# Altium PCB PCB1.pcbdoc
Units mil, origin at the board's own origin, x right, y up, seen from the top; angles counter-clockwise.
Board outline 3897.64 x 2283.46 mil, 4 copper layers (Top Layer, Inner1, Inner2, Bottom Layer), stack 62.447 mil thick; 82 components, 48 nets, 260 pads, 206 vias.
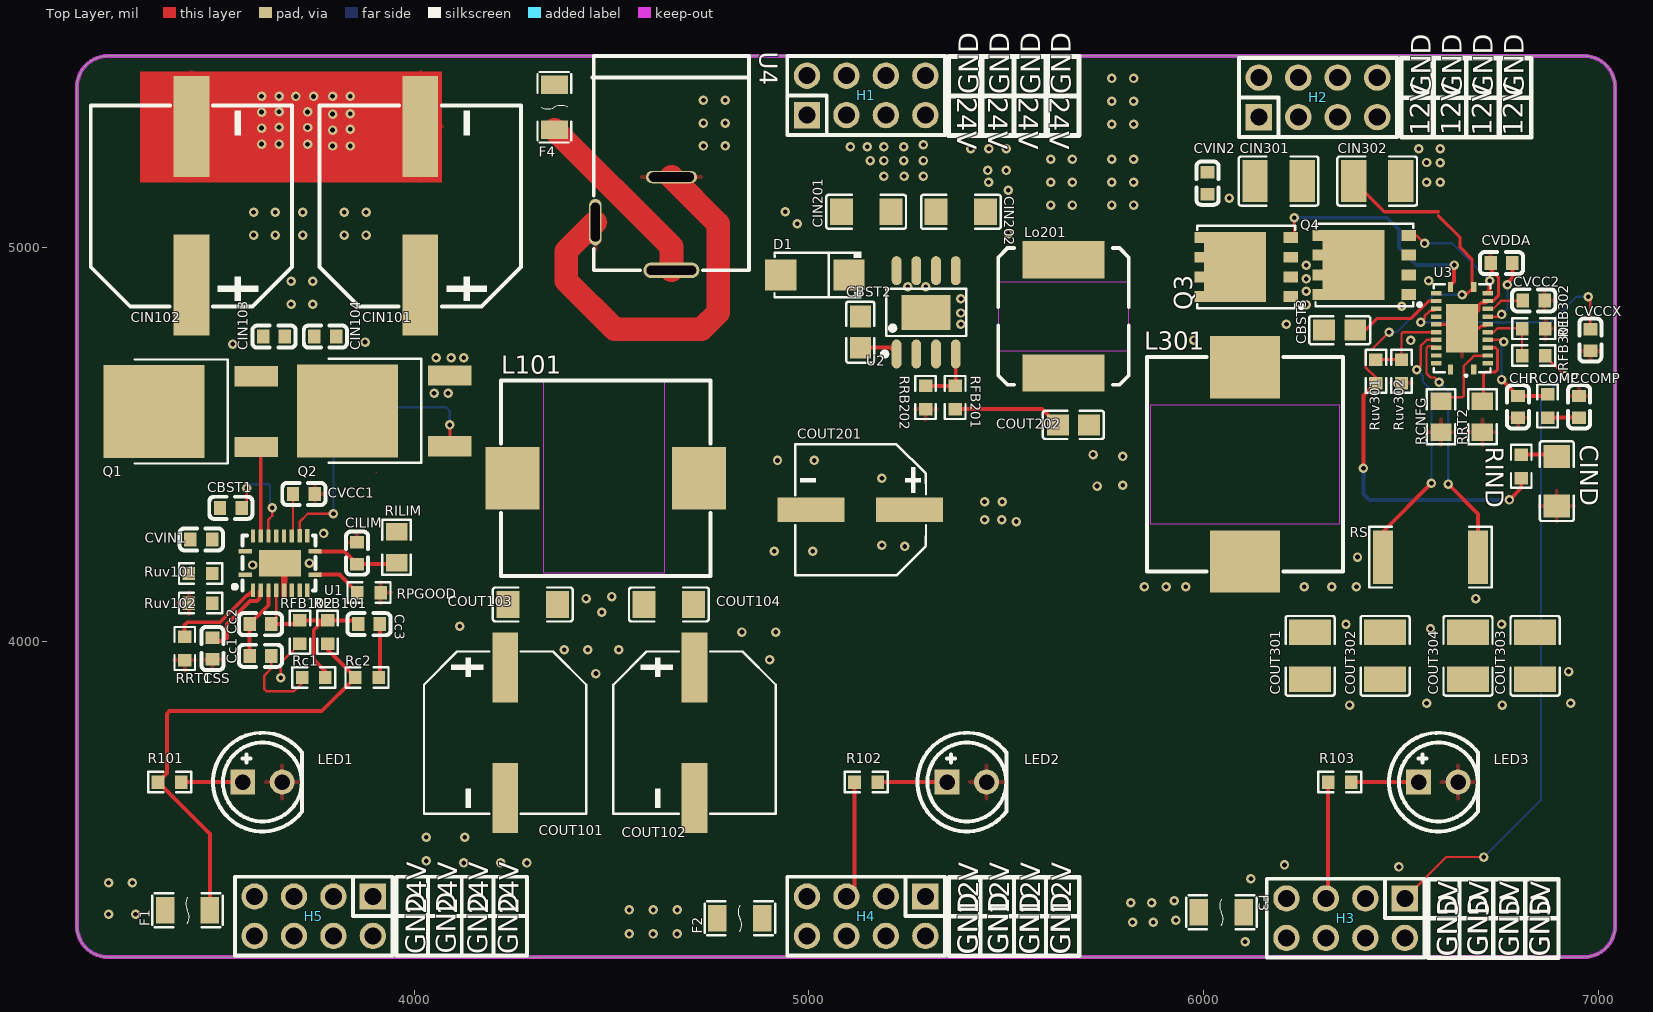
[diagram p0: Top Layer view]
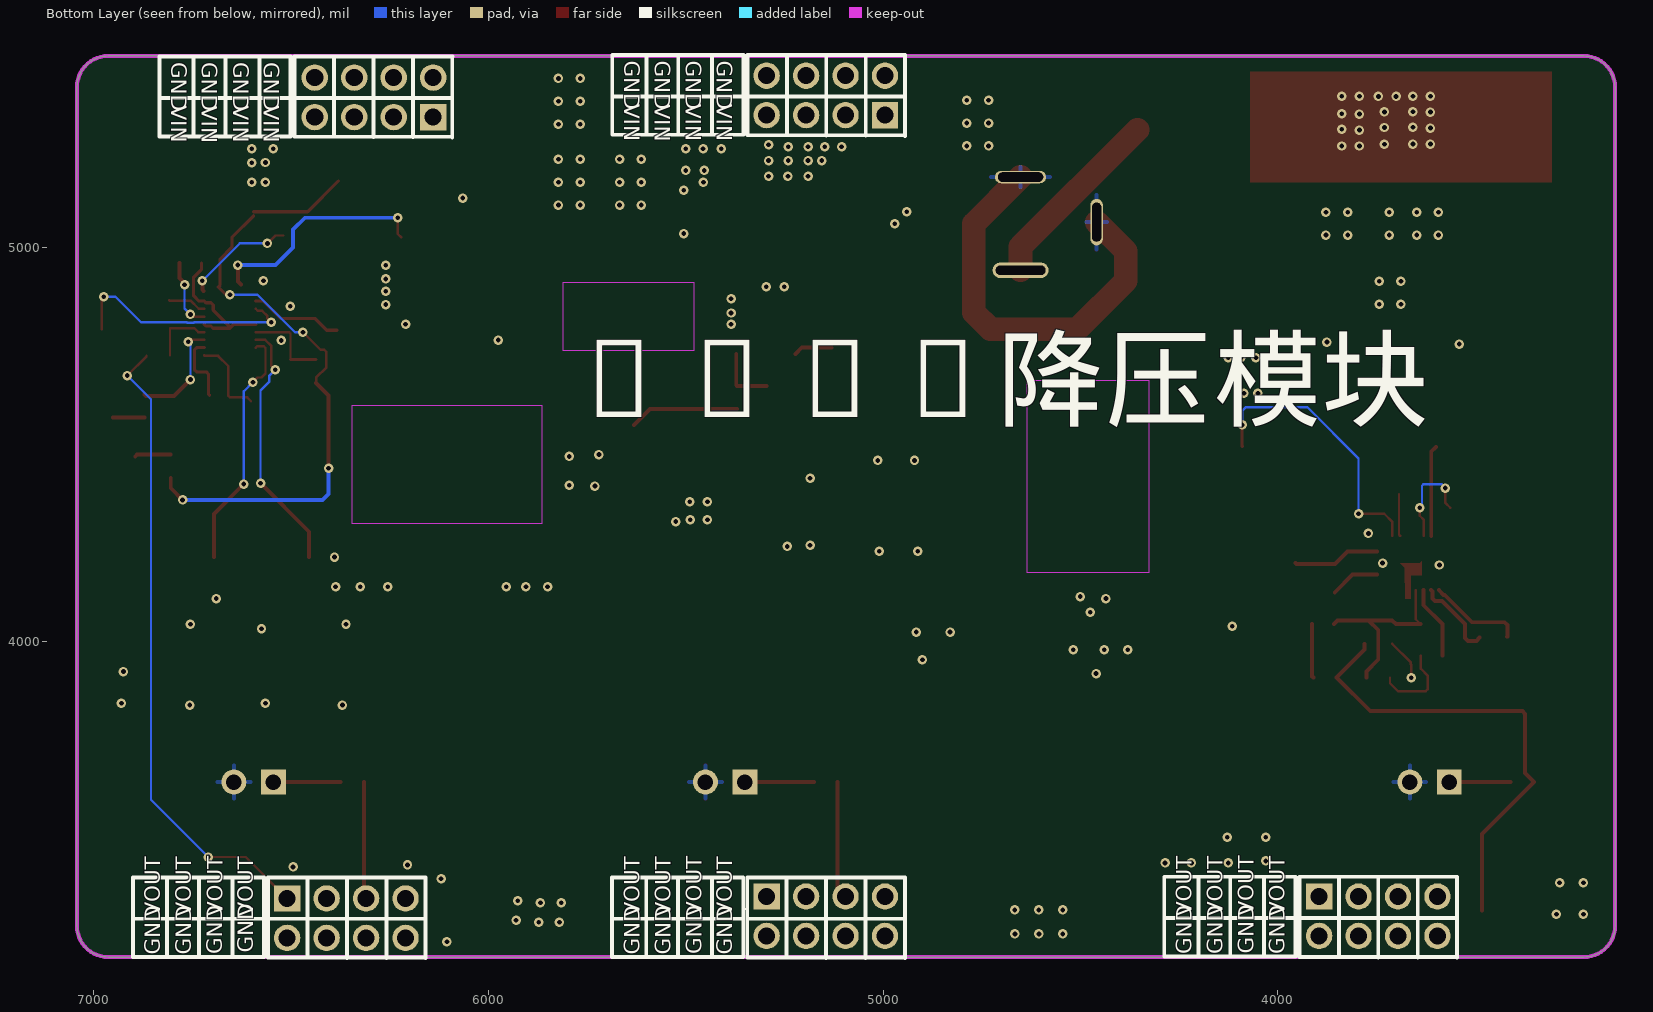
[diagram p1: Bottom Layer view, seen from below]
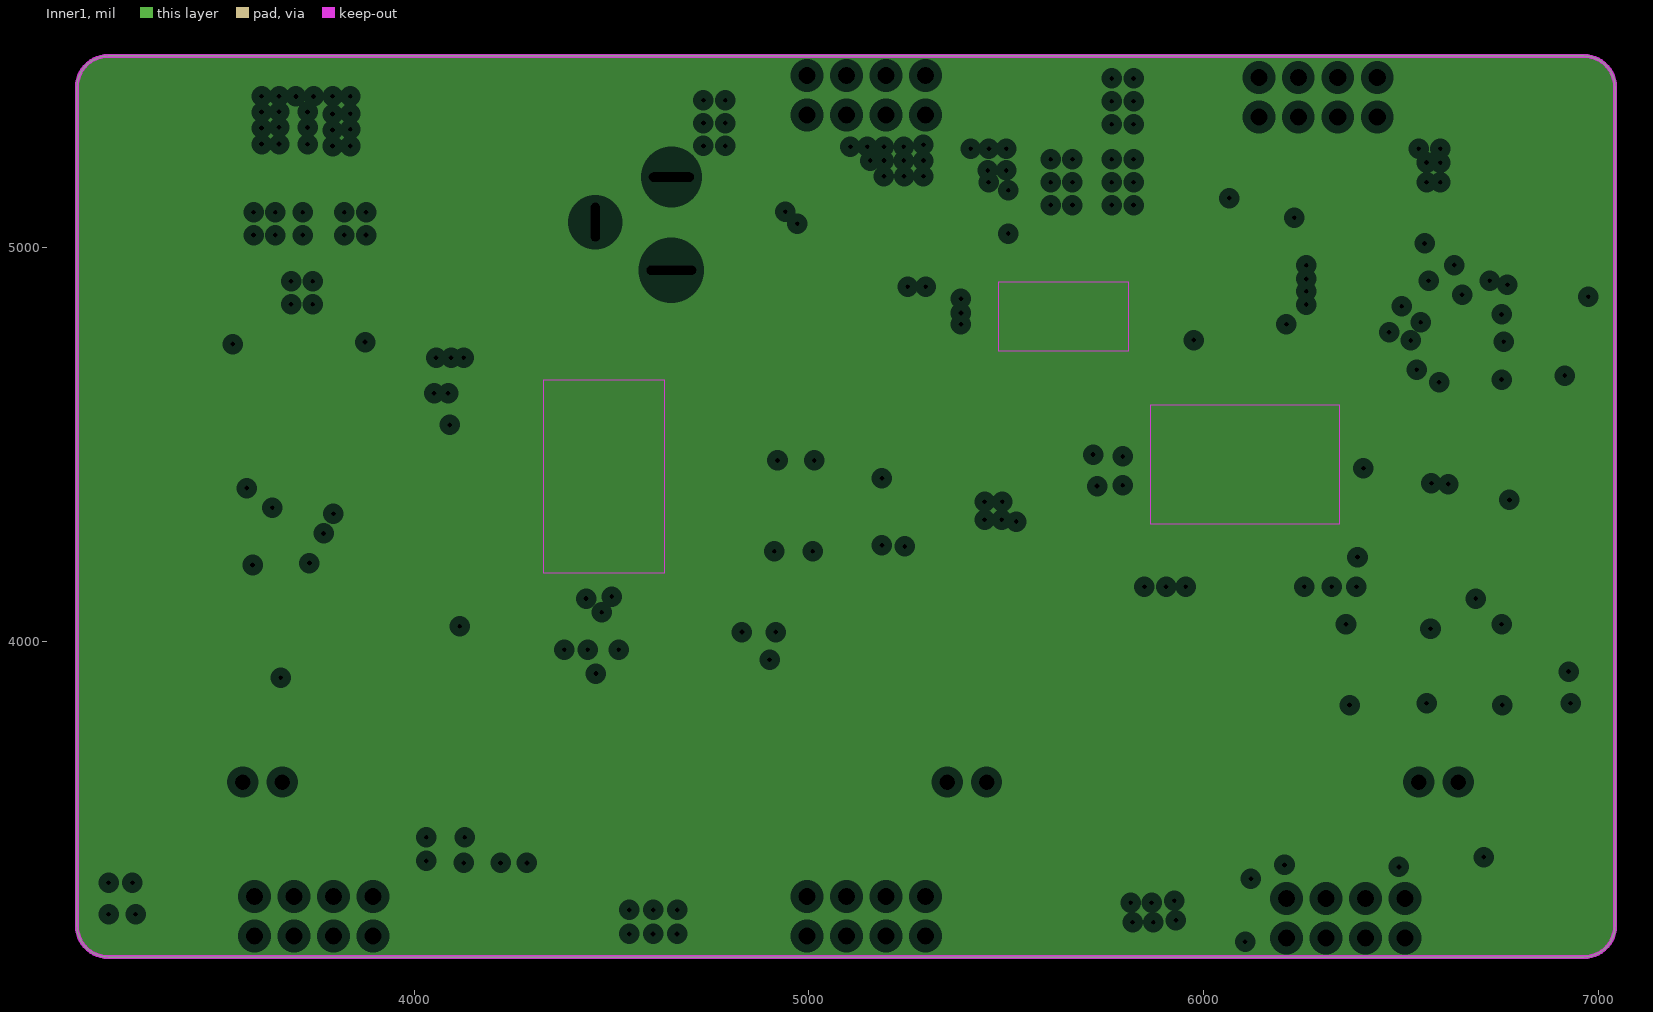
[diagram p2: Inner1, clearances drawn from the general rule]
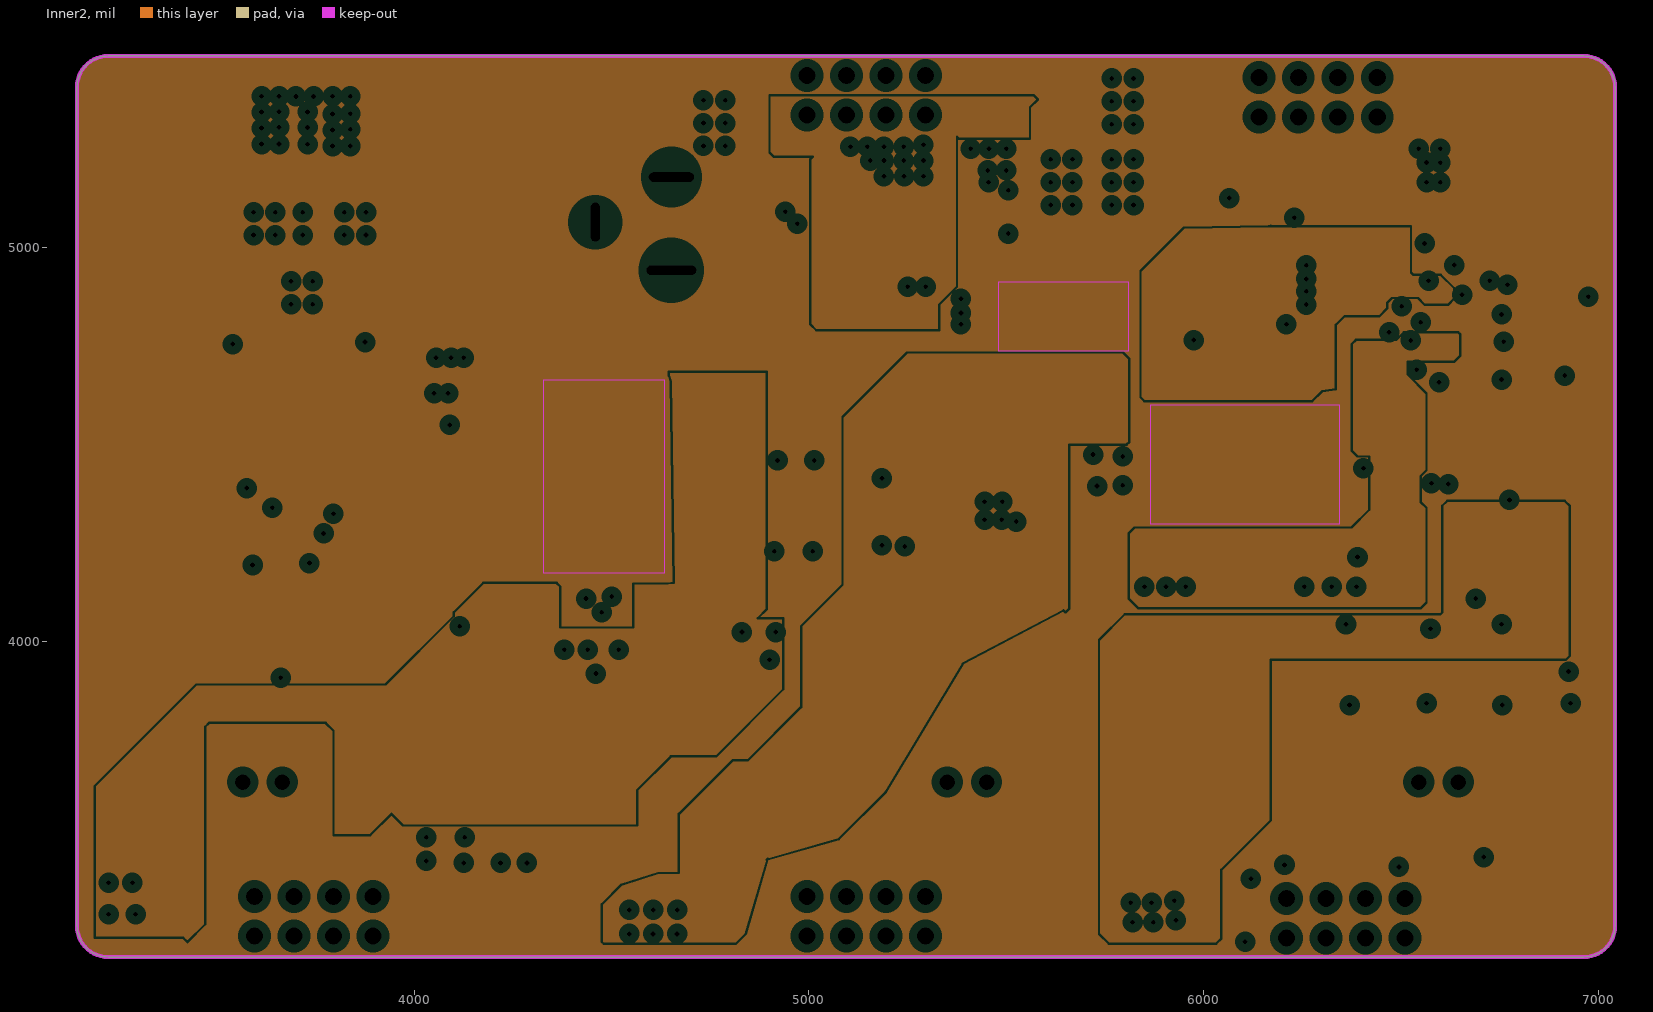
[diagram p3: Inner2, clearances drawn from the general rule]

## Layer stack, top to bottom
Top Layer: signal copper 1.378
Dielectric1: surface 8.283, 7628 RC49% 8.6mil, Dk 0
Inner1: plane copper 0.598
Dielectric2: surface 41.929, 1.1mm H/HOZ Copper, Dk 0
Inner2: plane copper 0.598
Dielectric3: surface 8.283, 7628 RC49% 8.6mil, Dk 0
Bottom Layer: signal copper 1.378

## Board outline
3223.74,5485 ccw(c3223.74,5406.26) 3145,5406.26 3145,3280.28 ccw(c3223.74,3280.28) 3223.74,3201.54 6963.9,3201.54 ccw(c6963.9,3280.28) 7042.64,3280.28 7042.64,5406.26 ccw(c6963.9,5406.26) 6963.9,5485 3223.74,5485

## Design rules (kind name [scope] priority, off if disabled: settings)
BoardOutlineClearance copperThickness1oz [All] p0: genericclearance=10 ignorepadtopadclearanceinfootprint=FALSE except(0: Arc-SplitContinuation Track-SplitContinuation SMDPad-SplitContinuation THPad-SplitContinuation Via-SplitContinuation Fill-SplitContinuation Poly-SplitContinuation Region-SplitContinuation Text-SplitContinuation)
BoardOutlineClearance copperThickness2oz [All] p0: genericclearance=10 ignorepadtopadclearanceinfootprint=FALSE except(0: Arc-SplitContinuation Track-SplitContinuation SMDPad-SplitContinuation THPad-SplitContinuation Via-SplitContinuation Fill-SplitContinuation Poly-SplitContinuation Region-SplitContinuation Text-SplitContinuation)
BoardOutlineClearance otherClearance [All] p0: genericclearance=10 ignorepadtopadclearanceinfootprint=FALSE except(0: Arc-SplitContinuation Track-SplitContinuation SMDPad-SplitContinuation THPad-SplitContinuation Via-SplitContinuation Fill-SplitContinuation Poly-SplitContinuation Region-SplitContinuation Text-SplitContinuation)
Clearance copperThickness1oz [All] p1: gap=7 ignorepadtopadclearanceinfootprint=FALSE
Clearance copperThickness2oz [All] p1: gap=7 ignorepadtopadclearanceinfootprint=FALSE
Clearance otherClearance [All] p1: gap=7 ignorepadtopadclearanceinfootprint=FALSE
DiffPairsRouting differentialPair [All] p1: maxuncoupledlength=10 minlimit=6 maxlimit=Infinity mostfreqgap=6 toplayer_minwidth=5 toplayer_prefwidth=10 toplayer_maxwidth=100 bottomlayer_minwidth=5 bottomlayer_prefwidth=10 bottomlayer_maxwidth=100
PasteMaskExpansion pasteMaskExpansion [All] p1: expansion=0
PlaneConnect innerPlane [All] p1: planeconnectstyle=Relief reliefexpansion=20 reliefentries=4 reliefconductorwidth=10 reliefairgap=10
PolygonConnect copperRegion [All] p1: connectstyle=Relief reliefentries=4 reliefconductorwidth=10 polygonreliefangle="90 Angle" airgapwidth=10
RoutingVias viaSize [All] p1: viastyle="Through Hole" holewidth=12.0078 minholewidth=11.811 maxholewidth=248.0314 width=12.0078 minwidth=11.811 maxwidth=248.0314
SolderMaskExpansion solderMaskExpansion [IsVia] p1: useseparateexpansions=TRUE expansion=-1000 expansionbottom=-1000
SolderMaskExpansion solderMaskExpansion [All] p2: useseparateexpansions=TRUE expansion=2 expansionbottom=2
Width copperThickness1oz [All] p1: maxlimit=100 minlimit=5 preferedwidth=10
Width copperThickness2oz [All] p1: maxlimit=100 minlimit=8 preferedwidth=10

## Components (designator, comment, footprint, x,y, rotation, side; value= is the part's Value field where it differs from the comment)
CBST1 "100nF" C0603 3535,4340 r180 top
CBST2 "10nF" C0805 5130,4785 r90 top
CBST3 "100nF" C0805 6345,4790 r0 top
Cc1 "4.7nF" C0603 3610,3965 r180 top
Cc2 "82pF" C0603 3610,4045 r180 top
Cc3 "1.8nF" C0603 3885,4045 r0 top
CCOMP "8.2nF" C0603 6951.61,4595.77 r270 top
CHF "180pF" C0603 6796.61,4595.77 r90 top
CILIM "4.7nF" C0603 3855,4225 r90 top
CIN101 "100uF" CAP-SMD_BD12.5-L13.0-W13.0-LS13.7-FD 4015,5105 r90 top
CIN102 "100uF" CAP-SMD_BD12.5-L13.0-W13.0-LS13.7-FD 3435,5105 r90 top
CIN103 "100nF" C0603 3644.38,4773.86 r0 top
CIN104 "100nF" C0603 3774.38,4773.86 r180 top
CIN201 "22uf" C1206 5145,5090 r0 top
CIN202 "10uF" C1206 5385,5090 r180 top
CIN301 "22uF" C1210 6190,5168 r0 top
CIN302 "22uF" C1210 6440,5168 r180 top
CIND "47uF" C1206 6895,4407.3 r90 top
COUT101 "220uF" CAP-SMD_BD10.0-L10.3-W10.3-LS11.7-FD 4230,3770 r270 top
COUT102 "220uF" CAP-SMD_BD10.0-L10.3-W10.3-LS11.7-FD 4710,3770 r270 top
COUT103 "10uF" C1206 4300,4095 r180 top
COUT104 "10uF" C1206 4645,4095 r0 top
COUT201 "220uF" CAP-SMD_BD8.0-L8.3-W8.3-LS9.3-FD-A 5130,4335 r180 top
COUT202 "10uF" C0805 5670,4550 r180 top
COUT301 "47uF" C1210 6270,3965 r90 top
COUT302 "47uF" C1210 6460,3965 r90 top
COUT303 "47uF" C1210 6840,3965 r90 top
COUT304 "47uF" C1210 6670,3965 r90 top
CSS "47nF" C0603 3488.27,3983.49 r90 top
CVCC1 "2.2uF" C0603 3720,4375 r0 top
CVCC2 "2.2uF" C0603 6836.61,4865.77 r0 top
CVCCX "100nF" C0603 6980,4765 r90 top
CVDDA "100nF" C0603 6755,4960 r0 top
CVIN1 "100nF" C0603 3460,4260 r180 top
CVIN2 "22nF" C0603 6010,5162.57 r270 top
D1 "SS36" SMA_L4.3-W2.6-LS5.2-RD 5015,4930 r180 top
F1 "JFC1206-1300FS" F1206 3425,3320 r0 top
F2 "JFC1206-1300FS" F1206 4825,3300 r0 top
F3 "JFC1206-1300FS" F1206 6045,3315 r0 top
F4 "JFC1206-1300FS" F1206 4355,5355 r90 top
H1 "" HDR-TH_8P-P2.54-V-M-R2-C4-S2.54 5145,5385 r0 top
H2 "" HDR-TH_8P-P2.54-V-M-R2-C4-S2.54 6290,5380 r0 top
H3 "" HDR-TH_8P-P2.54-V-M-R2-C4-S2.54 6360,3300 r180 top
H4 "" HDR-TH_8P-P2.54-V-M-R2-C4-S2.54 5145,3305 r180 top
H5 "" HDR-TH_8P-P2.54-V-M-R2-C4-S2.54 3745,3305 r180 top
L101 "XR1250-4R7M" IND-SMD_L13.5-W12.6 4485,4415 r0 top
L301 "SMMS1360-2R2M" IND-SMD_L13.8-W12.6_SMMS1360 6105,4450 r270 top
LED1 "" LED-TH_5mm 3615,3645 r0 top
LED2 "" LED-TH_5mm 5400,3645 r0 top
LED3 "" LED-TH_5mm 6595,3645 r0 top
Lo201 "33uH" IND-SMD_L8.2-W8.2-LS8.6 5645,4825 r270 top
Q1 "NCE0110K" TO-252-2_L6.6-W6.1-P4.57-LS9.9-TL-CW 3469.38,4583.86 r180 top
Q2 "NCE0110K" TO-252-2_L6.6-W6.1-P4.57-LS9.9-TL-CW 3960.05,4585.37 r180 top
Q3 "BSC027N04LSG" PG-TDSON-8_L5.0-W6.0-P1.27-LS6.2-BL-EP 6107.77,4949.99 r90 top
Q4 "BSC027N04LSG" PG-TDSON-8_L5.0-W6.0-P1.27-LS6.2-BL-EP 6407.48,4955.13 r90 top
R101 "2K" R0603 3380,3645 r0 top
R102 "1K" R0603 5145,3645 r0 top
R103 "330Ω" R0603 6345,3645 r0 top
Rc1 "10.2K" R0603 3745,3910 r0 top
Rc2 "107Ω" R0603 3880,3910 r180 top
RCNFG "41.2kΩ" R0805 6601.61,4570.77 r90 top
RCOMP "5.23kΩ" R0603 6871.61,4597.96 r90 top
RFB101 "22.1K" R0603 3780,4025 r270 top
RFB102 "768Ω" R0603 3710,4025 r270 top
RFB201 "10kΩ" R0603 5370.5,4619.5 r270 top
RFB301 "78.7kΩ" R0603 6836.61,4725.77 r180 top
RFB302 "15kΩ" R0603 6836.61,4793.87 r180 top
RILIM "19.6K" R0805 3955,4240 r90 top
RIND "250mΩ" R0603 6805,4445 r270 top
RPGOOD "20K" R0603 3885,4125 r180 top
RRB202 "1.13kΩ" R0603 5295.5,4619.5 r90 top
RRT1 "24.9K" R0603 3418.27,3983.49 r90 top
RRT2 "73.2kΩ" R0805 6706.61,4570.77 r90 top
RS "2mΩ" R2512 6575,4215 r0 top
Ruv101 "402K" R0603 3458.27,4173.49 r180 top
Ruv102 "14.7K" R0603 3458.27,4098.49 r0 top
Ruv301 "100kΩ" R0603 6436.61,4685.77 r90 top
Ruv302 "10.5kΩ" R0603 6501.61,4685.77 r270 top
U1 "LM5145RGYR" VQFN-20_L4.5-W3.5-P0.50-BL-EP 3660,4200 r0 top
U2 "TPS5430DDA" ESOP-8_L4.9-W3.9-P1.27-LS6.0-BL-EP-2 5296.93,4835.27 r0 top
U3 "LM5148RGYR" VQFN-24_L5.5-W3.5-P0.50-BL-EP-2 6655,4795 r90 top
U4 "DC-S006A-D020-5A" CONN-TH_DC-S006A-D020-5A 4555,5060 r270 top

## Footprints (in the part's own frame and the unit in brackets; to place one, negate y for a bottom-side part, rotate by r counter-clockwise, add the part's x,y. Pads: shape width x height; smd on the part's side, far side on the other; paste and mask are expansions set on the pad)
C0603 [mm]
  rect 0.8x0.9 smd: 1(-0.7,0) 2(0.7,0)
  silkscreen extent -1.39,-0.71 1.39,0.71
C0805 [mm]
  rect 1.41x1.35 smd paste-100 mask+0.051: 1(-1,0) 2(1,0)
  silkscreen extent -1.96,-0.9 1.96,0.9
C1206 [mm]
  rect 1.485x1.728 smd paste-100 mask+0.051: 1(-1.593,0) 2(1.593,0)
  silkscreen extent -2.56,-1.09 2.56,1.09
C1210 [mm]
  rect 1.635x2.7 smd paste-100 mask+0.051: 1(-1.517,0) 2(1.517,0)
  silkscreen extent -2.56,-1.58 2.56,1.58
CAP-SMD_BD8.0-L8.3-W8.3-LS9.3-FD-A [mm]
  rect 4.3x1.6 smd: 1(-3.173,0) 2(3.173,0)
  silkscreen extent -4.23,-4.23 4.18,4.23
CAP-SMD_BD10.0-L10.3-W10.3-LS11.7-FD [mm]
  rect 4.5x1.65 smd: 1(-4.2,0) 2(4.2,0)
  silkscreen extent -5.23,-5.23 5.23,5.23
CAP-SMD_BD12.5-L13.0-W13.0-LS13.7-FD [mm]
  rect 6.5x2.3 smd: 1(-5.1,0) 2(5.1,0)
  silkscreen extent -6.48,-6.48 6.48,6.48
CONN-TH_DC-S006A-D020-5A [mm]
  oval 1x3.6 hole 0.6 slot 3.2 at 90 deg paste+0 mask+0.05: 1(3,2.45)
  oval 0.8x3.3 hole 0.6 slot 2.9 at 90 deg paste+0 mask+0.05: 2(-3,2.45)
  oval 3x0.8 hole 0.6 slot 2.5 at 0 deg paste+0 mask+0.05: 3(-0.1,-2.45)
  silkscreen extent -10.8,-2.63 3,7.45
ESOP-8_L4.9-W3.9-P1.27-LS6.0-BL-EP-2 [mm]
  oval 0.63x1.865 smd: 1(-1.905,-2.683) 2(-0.635,-2.683) 3(0.635,-2.683) 4(1.905,-2.683) 5(1.905,2.682) 6(0.635,2.682) 7(-0.635,2.682) 8(-1.905,2.682)
  rect 3.15x2.26 smd paste+0 mask+0.05: 9(0,0)
  silkscreen extent -2.82,-2.83 2.58,1.52
F1206 [mm]
  rect 1.19x1.728 smd: 1(-1.445,0) 2(1.445,0)
  silkscreen extent -2.27,-1.09 2.27,1.09
HDR-TH_8P-P2.54-V-M-R2-C4-S2.54 [mm]
  rect 1.7x1.7 hole 1.1: 1(-3.81,-1.27)
  round 1.7 hole 1.1: 2(-3.81,1.27) 3(-1.27,-1.27) 4(-1.27,1.27) 5(1.27,-1.27) 6(1.27,1.27) 7(3.81,-1.27) 8(3.81,1.27)
  silkscreen extent -5.08,-2.54 5.08,2.54
IND-SMD_L8.2-W8.2-LS8.6 [mm]
  rect 2.4x5.3 smd: 1(-3.638,0) 2(3.638,0)
  silkscreen extent -4.4,-4.2 4.4,4.2
IND-SMD_L13.5-W12.6 [mm]
  rect 3.5x4 smd: 1(-6,0) 2(6,0)
  silkscreen extent -6.75,-6.3 6.75,6.3
IND-SMD_L13.8-W12.6_SMMS1360 [mm]
  rect 4x4.5 smd: 1(-6.25,0) 2(6.25,0)
  silkscreen extent -6.9,-6.3 6.9,6.3
LED-TH_5mm [mm]
  rect 1.6x1.6 hole 1 paste+0 mask+0.051: 1(-1.27,0)
  round 1.6 hole 1 paste+0 mask+0.051: 2(1.27,0)
  silkscreen extent -3.17,-3.17 2.54,3.17
PG-TDSON-8_L5.0-W6.0-P1.27-LS6.2-BL-EP [mm]
  rect 0.7x0.925 smd paste-100 mask+0.051: 1(-1.905,-2.865) 2(-0.635,-2.865) 3(0.635,-2.865) 4(1.905,-2.865) 5(1.905,2.865) 6(0.635,2.865) 7(-0.635,2.865) 8(-1.905,2.865)
  rect 4.5x4 smd paste-100 mask+0.05: 9(0,0.705)
  silkscreen extent -2.66,-3.66 2.65,3.15
R0603 [mil]
  rect 31.75x34.02 smd paste-3937.01 mask+2: 1(-29.66,0) 2(29.66,0)
  silkscreen extent -55,-26 55,26
R0805 [mil]
  rect 44.59x54.21 smd paste-3937.01 mask+2: 1(-39.37,0) 2(39.37,0)
  silkscreen extent -69,-36 69,36
R2512 [mil]
  rect 50.49x136.06 smd paste-3937.01 mask+2: 1(-120.72,0) 2(120.72,0)
  silkscreen extent -155,-77 155,77
SMA_L4.3-W2.6-LS5.2-RD [mm]
  rect 2x2 smd: 1(-2.2,0) 2(2.2,0)
  silkscreen extent -2.98,-1.5 2.6,1.5
TO-252-2_L6.6-W6.1-P4.57-LS9.9-TL-CW [mm]
  rect 2.8x1.3 smd: 1(-3.292,2.273) 3(-3.292,-2.273)
  rect 6.5x6 smd: 2(3.292,0)
  silkscreen extent -1.46,-3.35 4.51,3.34
VQFN-20_L4.5-W3.5-P0.50-BL-EP [mm]
  rect 0.85x0.28 smd: 1(-2.25,-0.752) 10(2.25,-0.752) 11(2.25,0.748) 20(-2.25,0.75)
  rect 0.28x0.85 smd: 2(-1.749,-1.75) 3(-1.248,-1.75) 4(-0.749,-1.75) 5(-0.248,-1.75) 6(0.251,-1.75) 7(0.752,-1.75) 8(1.251,-1.75) 9(1.752,-1.75) 12(1.752,1.75) 13(1.251,1.75) 14(0.75,1.748) 15(0.25,1.748) 16(-0.25,1.748) 17(-0.75,1.748) 18(-1.25,1.748) 19(-1.75,1.748)
  rect 2.7x1.7 smd: 21(0,-0.002)
  silkscreen extent -3.05,-1.78 2.29,1.78
VQFN-24_L5.5-W3.5-P0.50-BL-EP-2 [mm]
  rect 0.665x0.336 smd: 1(-2.657,-0.75) 12(2.657,-0.75) 13(2.657,0.75) 24(-2.657,0.75)
  rect 0.28x0.665 smd: 2(-2.25,-1.657) 3(-1.75,-1.657) 4(-1.25,-1.657) 5(-0.75,-1.657) 6(-0.25,-1.657) 7(0.25,-1.657) 8(0.75,-1.657) 9(1.25,-1.657) 10(1.75,-1.657) 11(2.25,-1.657) 14(2.25,1.657) 15(1.75,1.657) 16(1.25,1.657) 17(0.75,1.657) 18(0.25,1.657) 19(-0.25,1.657) 20(-0.75,1.657) 21(-1.25,1.657) 22(-1.75,1.657) 23(-2.25,1.657)
  rect 3.1x2.05 smd: 25(0,0)
  silkscreen extent -3.12,-1.83 2.83,1.83

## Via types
v1: diameter 24.02, hole 12, Top Layer to Bottom Layer, 206 vias

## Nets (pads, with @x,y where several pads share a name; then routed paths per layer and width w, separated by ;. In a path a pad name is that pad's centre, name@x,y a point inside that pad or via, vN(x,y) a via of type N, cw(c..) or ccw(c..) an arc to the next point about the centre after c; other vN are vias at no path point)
$1N88: LED1.1 R101.2 | length 155.3
  Top Layer w10: R101.2 LED1.1
$1N109: COUT201.1 COUT202.2 F2.1 Lo201.2 RFB201.2 | length 276.6
  Top Layer w10: RFB201.2 5590.79,4589.84 COUT202.2
  other v1: 4544.3,3260 4605,3260 4665.7,3260 4544.65,3320.85 4605.35,3320.85 4666.04,3320.85 5242.77,4242.17 5185,4245 5185,4415
$1N113: LED2.1 R102.2 | length 175.3
  Top Layer w10: R102.2 LED2.1
$1N116: LED3.1 R103.2 | length 170.3
  Top Layer w10: R103.2 LED3.1
$1N123: Cc1.1 Rc1.1 | length 212.8
  Top Layer w6: Cc1.1 3637.56,3932.56 3620,3915 3620,3880 3625,3875 3695,3875 3715.34,3895.34 Rc1.1
$1N125: Cc3.2 Rc2.1 | length 136.2
  Top Layer w10: Rc2.1 3912.56,3912.9 Cc3.2
$1N132: COUT101.1 COUT102.1 COUT103.2 COUT104.2 F1.1 L101.2
  other v1: 3225,3310 3293.59,3310 3225,3390 3285.7,3390 4460,3920 4900,3955 4380,3980 4439.51,3980 4517.86,3980 4830,4025 4915.87,4025 4115,4040
$1N150: F4.1 U4.1 | length 479
  Top Layer w60: F4.1 4651.45,5001.65 U4.1
$2N64: CCOMP.2 RCOMP.1 | length 80
  Top Layer w10: RCOMP.1 6951.52,4568.3 CCOMP.2
$2N105: CIND.2 RIND.1 | length 91.9
  Top Layer w10: RIND.1 6890.34,4474.66 CIND.2
BOOT_24V: CBST2.1 U2.1 | length 98.5
  Top Layer w10: CBST2.1 5205.96,4745.63 U2.1
BST_48V: CBST1.1 U1.17 | length 254
  Top Layer w6: CBST1.1 3575,4352.44 v1(3575,4390) ; U1.17 3630,4269.29 3630,4310 3640,4320 v1(3640,4340)
  Bottom Layer w6: v1(3575,4390) 3585,4400 3630,4400 3634.24,4395.76 3634.24,4345.76 v1(3640,4340)
CBOOT: CBST3.2 U3.15 | length 236
  Top Layer w8: CBST3.2 6410,4790 6440,4820 6526.4,4820 6570.3,4863.9 U3.15
CNFG: RCNFG.2 U3.3 | length 210.6
  Top Layer w6: RCNFG.2 6611.47,4620 6655,4620 6659.24,4624.24 6659.24,4699.24 6685,4725 6719.16,4725 U3.3
COMP_48V: Cc1.2 Cc2.2 U1.4 | length 186
  Top Layer w10: Cc1.2 Cc2.2 3630.53,4093.09 U1.4
EN: Ruv301.2 Ruv302.1 U3.19 | length 220.8
  Top Layer w6: Ruv302.1 6501.61,4781.61 6505,4785 6589.59,4785 U3.19
  Top Layer w8: Ruv301.2 Ruv302.1
EN/UVLO_48V: Ruv101.1 Ruv102.2 U1.1
ENA: U2.5
EXTCOMP_12V: CHF.2 RCOMP.2 U3.5 | length 275.9
  Top Layer w6: U3.5 6755.73,4765.47 v1(6760.6,4760.6)
  Top Layer w10: v1(6755,4665) CHF.2@6796.61,4623.39 ; CHF.2 6867.31,4623.33 RCOMP.2
  Bottom Layer w6: v1(6755,4665) 6755,4755 v1(6760.6,4760.6)
FB_12V: RFB301.2 RFB302.2 U3.6 | length 159.3
  Top Layer w6: U3.6 6735.15,4785.15 6745,4795 6805.81,4795 RFB302.2 RFB301.2
FB_48V: Cc2.1 Cc3.1 Rc1.2 RFB101.1 RFB102.1 U1.5 | length 486.4
  Top Layer w6: Cc2.1 3650.22,4057.66 U1.5
  Top Layer w10: Cc2.1 3700.34,4045 RFB102.1 RFB101.1@3769.66,4054.66 ; Rc1.2 3774.66,3925.34 3745,3955 3745,4030 RFB101.1@3769.66,4054.66 ; Cc3.1 3847.78,4054.66 RFB101.1 RFB101.1@3769.66,4054.66
GND: CCOMP.1 CHF.1 CILIM.2 CIN101.2 CIN102.2 CIN103.1 CIN104.1 CIN201.1 CIN202.1 CIN301.1 CIN302.1 CIND.1 COUT101.2 COUT102.2 COUT103.1 COUT104.1 COUT201.2 COUT202.1 COUT301.1 COUT302.1 COUT303.1 COUT304.1 CSS.1 CVCC1.2 CVCC2.2 CVCCX.1 CVDDA.1 CVIN2.2 D1.2 H1.2 H1.4 H1.6 H1.8 H2.2 H2.4 H2.6 H2.8 H3.2 H3.4 H3.6 H3.8 H4.2 H4.4 H4.6 H4.8 H5.2 H5.4 H5.6 H5.8 LED1.2 LED2.2 LED3.2 Q2.3 Q4.1 Q4.2 Q4.3 RCNFG.1 RFB102.2 RFB302.1 RPGOOD.1 RRB202.1 RRT1.1 RRT2.1 Ruv102.1 Ruv302.2 U1.6 U1.12 U1.15 U1.21 U2.6 U2.9 U3.7 U3.10 U3.18 U3.25 U4.2 U4.3 | length 1496.4
  Top Layer w6: v1(3661.15,3909.56) 3661.15,3942.42 3662.29,3943.56 3662.29,3947.63 RFB102.2
  Top Layer w8: U3.18 6645.16,4804.84 U3.25 ; U3.7 6716.07,4800.65 6703.03,4800.65 6697.37,4794.99 U3.25 ; CVDDA.1 6727.44,4943.68 6747.01,4924.12 6747.01,4877.01 6733.9,4863.9 U3.10 6716.06,4859.7 6703.03,4859.7 6697.18,4853.85 6697.18,4840.82 6655.01,4798.65 U3.25
  Top Layer w60: U4.3 4385,4990.39 4385,4915 4507.43,4792.57 4727.57,4792.57 4770,4835 4770,5059.56 U4.2
  other v1: 4125,3440 4218.53,3440 4285.38,3440 4030,3445 4030,3505 4127.64,3505 6370,3840 6756.81,3840 6565,3845 6930,3845 6925,3925 4475,4075 4435,4110 4500,4115 3590,4195 3733.98,4200 4911.85,4230 5009.75,4230 3770,4275 5525,4305 5445,4310 5488.76,4310 5445,4355 5490,4355 5730,4395 5795,4396.86 4920.25,4460 5013.15,4460 5795,4470 5720,4475 4050,4630 4085.49,4630 4055,4720 4093,4720 4125,4720 3540,4755 3875,4760 5385,4805.32 5385,4833.59 6502.1,4850.88 5385,4870 5505,5035 4970,5060 4940,5090 5612.5,5107.1 5667.5,5107.1 5767.5,5107.1 5822.5,5107.1 6065,5125 5505,5145 5455,5165 5612.5,5165 5667.5,5165 5767.5,5165 5822.5,5165 6565,5165 6600,5165 5453.33,5195 5500,5195 6600,5214.43 6565,5215 5612.5,5222.9 5667.5,5222.9 5767.5,5222.9 5822.5,5222.9 5410,5250 5455.97,5250 5500,5250 6545,5250 6600,5250 3792.77,5256.8 3837.23,5256.8 4732.5,5257.1 4787.5,5257.1 3729.47,5261.11 3612.77,5261.8 3657.23,5261.8 3792.77,5297.27 3837.23,5299.41 3612.77,5302.27 3657.23,5304.41 3729.47,5303.71 5767.5,5312.1 5822.5,5312.1 4732.5,5315 4787.5,5315 3792.77,5337.73 3837.23,5338.8 3612.77,5342.73 3729.47,5343.11 3657.23,5343.8 5767.5,5370 5822.5,5370 4732.5,5372.9 4787.5,5372.9 3700,5382.5 3744.47,5382.5 3612.77,5383.2 3657.23,5383.2 3792.77,5383.2 3837.23,5383.2 5767.5,5427.9 5822.5,5427.9
HO_12V: Q3.4 U3.13 | length 587.9
  Top Layer w6: Q3.4 6230,5034.42 v1(6230,5075)
  Top Layer w10: U3.13@6627.08,4905.4 6635,4913.31 v1(6635,4955)
  Bottom Layer w10: v1(6230,5075) 6465,5075 6495,5045 6495,5000 6540,4955 v1(6635,4955)
HO_48V: Q1.1 U1.18 | length 230.4
  Top Layer w10: Q1.1 3610.79,4482.57 U1.18
ILIM_48V: CILIM.1 RILIM.1 U1.11 | length 221
  Top Layer w10: U1.11 3822.99,4229.45 CILIM.1 3951.81,4197.44 RILIM.1
ISNS+: L301.2 RS.1 U3.20 | length 651.9
  Top Layer w6: v1(6540,4690) 6550,4700 6550,4750 6565.47,4765.47 U3.20
  Top Layer w10: RS.1 6454.28,4279.28 v1(6577.5,4402.5)
  Bottom Layer w6: v1(6540,4690) 6555,4675 6555,4660 6577.5,4637.5 v1(6577.5,4402.5)
  other v1: 5850,4140 5905,4140 5955,4140 6255,4140 6325,4140 6387.24,4140 6390,4215 6525,4763.99
LO_12V: Q4.4 U3.11 | length 279.4
  Top Layer w6: Q4.4 6539.87,5030.13 v1(6560,5010)
  Top Layer w10: 6721.86,4889.35 6725,4892.48 v1(6725,4915)
  Bottom Layer w6: v1(6560,5010) 6630,5010 v1(6725,4915)
LO_48V: Q2.1 U1.13 | length 711.9
  Top Layer w6: U1.13 3709.27,4304.27 3730,4325 v1(3795,4325)
  Top Layer w8: Q2.1 4090,4496.24 v1(4090,4550)
  Bottom Layer w6: v1(3795,4325) 3795,4465 3925,4595 4080,4595 4090,4585 v1(4090,4550)
NC: U1.16
PGOOD_48V: RPGOOD.2 U1.10 | length 125.6
  Top Layer w10: U1.10 3809.95,4170.39 RPGOOD.2
PH: CBST2.2 D1.1 Lo201.1 U2.8
RT_12V: RRT2.2 U3.4 | length 172.2
  Top Layer w8: RRT2.2@6706.61,4625.14 6709.34,4627.88 6709.34,4678.69 6715,4684.34 6739.34,4684.34 6745,4690 6745,4740 6739.22,4745.78 U3.4
RT_48V: RRT1.2 U1.2 | length 239.7
  Top Layer w10: RRT1.2 3417.93,4013.5 3417.93,4042.93 3425,4050 3507.12,4050 3576.51,4119.38 3579.44,4119.38 U1.2
SS/TRK_48V: CSS.2 U1.3 | length 210.3
  Top Layer w10: CSS.2 3496.4,4002.93 3517.93,4002.93 3525,4010 3525,4045.25 3583.13,4103.38 3601.22,4103.38 3607.66,4109.82 3607.66,4127.91 U1.3
SW_12V: CBST3.1 L301.1 Q3.1 Q3.2 Q3.3 Q4.5 Q4.6 Q4.7 Q4.8 Q4.9 U3.14
  other v1: 5975,4765 6210,4805 6260,4855 6260,4888.63 6570,4915 6260,4919.91 6260,4954.29
SW_48V: CBST1.2 L101.1 Q1.3 Q2.2 RILIM.2 U1.19
VCC_12V: CVCC2.1 U3.9 | length 97.7
  Top Layer w6: U3.9 6734.2,4844.2 6755,4865 6808.28,4865 CVCC2.1
VCC_48V: CVCC1.1 U1.14 | length 107.4
  Top Layer w6: U1.14 3692.44,4271.73 CVCC1.1
VCCX_12V: CVCCX.2 U3.16 | length 594.7
  Top Layer w6: v1(6550,4810) 6560,4820 6560,4826.09 6572.93,4839.02 6584.56,4839.02 U3.16 ; v1(6975,4875) 6980,4870 CVCCX.2
  Bottom Layer w6: v1(6550,4810) 6745.29,4810 6746.3,4808.99 6763.7,4808.99 6764.71,4810 6880,4810 6945,4875 v1(6975,4875)
VDDA_12V: CVDDA.2 U3.8 | length 178.4
  Top Layer w6: U3.8 6749.52,4824.52 v1(6755,4830)
  Top Layer w10: v1(6770,4905) 6770,4910 6782.56,4922.56 CVDDA.2
  Bottom Layer w6: v1(6755,4830) 6770,4845 v1(6770,4905)
VIN_12V: CIN301.2 CIN302.2 CVIN2.1 H2.1 H2.3 H2.5 H2.7 Q3.5 Q3.6 Q3.7 Q3.8 Q3.9 RIND.2 Ruv301.1 U3.12 | length 1634.5
  Top Layer w6: Ruv301.1 6436.61,4669.84 6410.61,4695.83 6410.61,4735.03 6415.88,4740.29 6425.29,4740.29 v1(6470,4785)
  Top Layer w8: CIN302.2 6458.26,5090 6595,5090 ; 6595,5080 6650,5025 6650,5000 6680,4970 6680,4904.16 U3.12 6664.91,4880 v1(6655,4880)
  Top Layer w10: v1(6405,4440) 6405,4624.5 Ruv301.1 ; v1(6775,4360) 6805,4390 RIND.2
  Bottom Layer w6: v1(6470,4785) 6490,4785 6585,4880 v1(6655,4880)
  Bottom Layer w10: v1(6405,4440) 6405,4375 6420,4360 v1(6775,4360)
VIN_24V: CIN201.2 CIN202.2 H1.1 H1.3 H1.5 H1.7 U2.7
  other v1: 5250,4900 5295.63,4900.17 5190,5180 5240.86,5180 5290,5180 5155,5220 5190,5220 5240,5220 5290,5220 5105,5255 5147.67,5255 5190,5255 5240,5255 5290,5259.85
VIN_48V: CIN101.1 CIN102.1 CIN103.2 CIN104.2 CVIN1.1 CVIN1.2 F4.2 Q1.2 Ruv101.2 U1.20
  other v1: 3687.5,4856.05 3742.5,4856.05 3687.5,4913.95 3742.5,4913.95 3592.5,5031.05 3647.5,5031.05 3717.5,5031.05 3822.5,5031.05 3877.5,5031.05 3592.5,5088.95 3647.5,5088.95 3717.5,5088.95 3822.5,5088.95 3877.5,5088.95
VOUT: COUT301.2 COUT302.2 COUT303.2 COUT304.2 F3.1 RS.2 U3.21 | length 617.9
  Top Layer w6: U3.21 6586.29,4749.24 6569.24,4749.24 6565,4745 6565,4680 6575,4670 6585,4670 v1(6596.58,4658.42)
  Top Layer w10: v1(6620,4400) 6695.72,4324.28 RS.2
  Bottom Layer w6: v1(6596.58,4658.42) 6620,4635 v1(6620,4400)
  other v1: 5820,3290 5872.5,3290 5930,3295 5815.55,3339.34 5868.05,3339.34 5925.55,3344.34 6575,4033.31 6360.87,4045 6755,4045 6690,4110
VOUT_5V: F3.2 H3.1 H3.3 H3.5 H3.7 R103.1 RFB301.1 | length 1916.6
  Top Layer w6: H3.1 6615,3455 v1(6710,3455) ; RFB301.1 6866.27,4723.73 v1(6915,4675)
  Top Layer w10: H3.5 6315.34,3355.34 R103.1
  Bottom Layer w6: v1(6710,3455) 6855,3600 6855,4615 v1(6915,4675)
  other v1: 6105,3240 6120,3400 6495,3430 6205,3435
VOUT_12V: F2.2 H4.1 H4.3 H4.5 H4.7 R102.1 | length 298.4
  Top Layer w10: H4.5 5115.34,3375.34 R102.1
VOUT_24V: F1.2 H5.1 H5.3 H5.5 H5.7 R101.1 Rc2.2 RFB101.2 | length 1191.8
  Top Layer w10: F1.2 3481.89,3513.45 R101.1 3372.93,3667.59 3372.93,3817.93 3380,3825 3765.34,3825 Rc2.2 3780,3980.34 RFB101.2
VSNS: RFB201.1 RRB202.2 U2.4 | length 156.1
  Top Layer w10: RRB202.2 RFB201.1 5371.93,4650.6 U2.4
pads on no net: U1.7 U1.8 U1.9 U2.2 U2.3 U3.1 U3.2 U3.17 U3.22 U3.23 U3.24

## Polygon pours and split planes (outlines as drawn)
VIN_48V on Top Layer (solid, remove dead copper, pour order 0): 4415,5460 4415,5360.79 4404.21,5350 4280,5350 4275,5355 4240,5320 4240,4750 3900,4750 3893.67,4828.67 3810,4820 3770,4820 3770,4731.34 3641.34,4731.34 3639.38,4729.38 3639.38,4821.24 3556.24,4821.24 3490,4755 3490,4425 3465,4400 3395,4400 3395,4300 3400,4295 3505,4295 3541.16,4258.84 3557.92,4250 3567.22,4240.7 3595,4240 3595,4211.65 3521.65,4211.65 3515,4205 3510,4210 3195,4210 3195,4730 3190,4735 3190,5120 3195,5125 3560,5125 3565,5130 4065,5130 4100,5165 4100,5425 4120,5445 4400,5445
VOUT_24V on Top Layer (solid, remove dead copper, pour order 98): 3445,3410 3462.74,3427.74 3945,3427.74 3962.77,3409.97 3962.77,3305 3570,3305 3530,3265 3455,3265 3445,3275
GND on Top Layer (solid, remove dead copper, pour order 100): 4015,4735 4155,4735 4155,4680 4150,4675 4150,4650 4115,4615 4030,4615 4030,4720
GND on Top Layer (solid, remove dead copper, pour order 104): 3560,4815 3630,4815 3635,4810 3635,4740 3630,4735 3535,4735 3520.8,4749.2 3527.1,4782.1
GND on Top Layer (solid, remove dead copper, pour order 106): 3865,4811.82 3865,4800 3875,4790 3890,4772.98 3890,4750 3870,4730 3780,4730 3780,4811.82
GND on Top Layer (solid, remove dead copper, pour order 110): 3630,4210 3630,4190 3615,4175 3610,4180 3580,4180 3576.58,4183.42 3575,4183.42 3575,4205 3580,4210
GND on Top Layer (solid, remove dead copper, pour order 112): 3709.27,4215.62 3754.38,4215.62 3760,4210 3760,4185 3715,4185 3710,4180 3710,4214.89
GND on Top Layer (solid, remove dead copper, pour order 120): 3565,3290 3930,3290 3930,3285 3935,3280 3935,3220 3930,3215 3560,3215 3555,3220 3555,3280
VIN_48V on Top Layer (solid, remove dead copper, pour order 122): 3409.25,4287.95 3409.25,4147.49 3458.27,4147.49 3458.27,4287.95
EN/UVLO_48V on Top Layer (solid, remove dead copper, pour order 124): 3470,4200 3523.04,4200 3523.04,4186.96 3525,4185 3551.46,4185 3551.46,4183.54 3555,4180 3591.32,4180 3591.32,4156.49 3551.49,4156.49 3550,4155 3525,4155 3525,4085 3520,4080 3510,4080 3505,4075 3458.27,4075 3458.27,4123.27 3465,4130 3465,4195
VIN_24V on Top Layer (solid, remove dead copper, pour order 126): 4924.23,5385 5335,5385 5340,5390 5340,5185 5345,5180 5380,5180 5385,5175 5385,5055 5375,5045 5301.99,5045 5290.07,5046.98 5268.73,5040.51 5258.19,5036.23 5242.55,5045 5152.35,5045 5140,5165 5145,5170 5055,5260 4920,5260 4924.23,5264.23
PH on Top Layer (solid, remove dead copper, pour order 128): 5015,5008.12 5126.88,5008.12 5130,5005 5130,4990 5155,4965 5175,4965 5195,4985 5240,4985 5233.18,4901.82 5195,4890 5160,4855 5160,4795.87 5159.36,4790 5045,4790 5045,4795.4 5040,4850 5015,4875
VOUT_12V on Top Layer (solid, remove dead copper, pour order 134): 4835,3420 4860,3445 5350,3445 5350,3300 5345,3305 4975.87,3305 4918.13,3228.27 4835,3228.27
GND on Top Layer (solid, remove dead copper, pour order 136): 4985,3295 5335,3295 5335,3215 4960,3215 4955,3220 4955,3280 4970,3280
GND on Top Layer (solid, remove dead copper, pour order 138): 4955,5475 5345,5475 5345,5395 5340,5390 4970,5390 4955,5405
GND on Top Layer (solid, remove dead copper, pour order 142): 5211.93,4789.36 5230.32,4807.75 5230.32,4885 5316.67,4885 5305,4915 5306.23,4985 5345,4985 5345,4900 5349.83,4895.17 5405.17,4895.17 5410,4900 5410,4789.36
GND on Top Layer (solid, remove dead copper, pour order 148): 5405,5160 5405,5020 5520,5020 5520,5160
PH on Top Layer (solid, remove dead copper, pour order 150): 5800,5020 5800,4915 5450,4915 5450,4935 5395,4990 5240,4990 5240,4915 5235,4910 5185,4910 5185,5015 5515,5015 5520,5010 5541.07,5031.07 5552.14,5020
VIN_24V on Top Layer (solid, remove dead copper, pour order 152): 5236.64,4895.17 5235,4896.81 5235,4905.6 5245.86,4916.46 5245.86,4987.37 5299.08,4987.37 5299.08,4915.92 5310,4905 5310,4900.99 5310.6,4900.39 5310.6,4890.6 5304.62,4884.62 5290.38,4884.62 5285,4890 5280.71,4890 5279.59,4891.12 5279.59,4900 5265,4900 5265,4892.25 5257.75,4885 5245,4885 5236.64,4893.36
VOUT on Top Layer (solid, remove dead copper, pour order 166): 5805,3375 6040,3375 6045,3370 6045,3230 6020,3205 5800,3205 5805,3210
VOUT_5V on Top Layer (solid, remove dead copper, pour order 172): 6065,3410 6130,3475 6525,3475 6555,3445 6555,3305 6550,3310 6165,3310 6165,3220 6155,3210 6150,3215 6070,3215 6065,3220
GND on Top Layer (solid, remove dead copper, pour order 174): 6173.96,3300 6548.47,3300 6548.47,3211.53 6550,3210 6180,3210 6175,3215 6175,3230 6170,3235 6170,3270 6175,3275 6173.96,3276.04
GND on Top Layer (solid, remove dead copper, pour order 176): 5965,5085 5965,5150 5970,5155 6075,5155 6085,5165 6085,5245 6090,5240 6180,5240 6180,5090 6175,5085
GND on Top Layer (solid, remove dead copper, pour order 178): 6500.03,5400.29 6100,5400.29 6100,5470 6500,5470 6505,5475 6645,5335 6645,5100 6465,5100 6455,5110 6455,5220 6515,5280 6520,5280 6520,5379.05 6500.03,5399.02
GND on Top Layer (solid, remove dead copper, pour order 180): 5415,5120 5415,5185 5380,5220 5380,5400 5375,5405 5245,5405 5245,5475 5490,5475 5520,5445 5520,5125 5515,5120
GND on Top Layer (solid, remove dead copper, pour order 182): 6490,4995 6545,4995 6545,4835 6487.54,4835
VIN_12V on Top Layer (solid, remove dead copper, pour order 184): 5915,5395 6481.84,5395 6481.84,5307.05 6469.79,5295 6465,5295 6435,5265 6435,5120 6440,5115 6443.97,5115 6461.9,5097.07 6517.93,5097.07 6520,5095 6640,5095 6660,5075 6660,5010 6690,4980 6695.2,4892.68 6667.67,4892.68 6670,4945 6665,4950 6665,4965 6611,5019 6580,5035 6535,5080 6300,5080 6290,5090 6265,5090 6260,5095 6225,5095 6181.31,5051.31 6180,4850 5895,4850 5875,4870 5875,5025 5930,5080 6175,5080 6185,5090 6185,5260.18 6180.18,5265 6075,5265 6075,5180 6065,5170 5935,5170 5930,5165 5930,5380
SW_12V on Top Layer (solid, remove dead copper, pour order 188): 6564.15,4873.04 6556.39,4883.61 6556.39,4927.47 6610,4927.47 6610,4873.04
SW_48V on Top Layer (solid, remove dead copper, pour order 190): 3600,4245 3570,4245 3525,4290 3508.22,4312.06 3442.94,4312.06 3425,4330 3425,4370 3434.72,4379.72 3540,4379.72 3540,4300 3600,4300
SW_48V on Top Layer (solid, remove dead copper, pour order 192): 3904.67,4430 3903.33,4429.25 3903.27,4430
SW_48V on Top Layer (solid, remove dead copper, pour order 194): 3910,4340 3903.33,4429.25 3900,4427.39 3683.07,4445 3670,4458.07 3662.23,4551.47 3540,4551.47 3530,4465 3574.09,4445 3525,4330 3520,4325 3465,4325 3470,4330 3470,4375 3495,4400 3495,4420 3505,4430 3505,4690 3540,4725 4000,4725 4015,4710 4015,4470 4020,4465 4150,4465 4170,4485 4170,4670 4176.97,4663.03 4309.53,4663.03 4317.89,4654.67 4317.89,4166.97 4310.92,4160 4135,4160 4135,4185 4075,4245 3900,4245 3900,4330
$1N132 on Top Layer (solid, remove dead copper, pour order 196): 4995,3785 4080,3785 4080,4140 4090,4150 4290,4150 4300,4140 4300,4040 4305,4035 4625,4035 4640,4050 4640,4710 4840,4710 4799.92,4669.92 4799.92,4166.97 4833.03,4166.97 4995,4005
$1N132 on Top Layer (solid, remove dead copper, pour order 198): 3190,3425 3410,3425 3410,3255 3405,3250 3205,3250 3185,3270 3190,3275
GND on Top Layer (solid, remove dead copper, pour order 200): 4320,4145 4620,4145 4625,4150 4625,4050 4615,4040 4335,4040 4325,4050 4325,4140
GND on Top Layer (solid, remove dead copper, pour order 202): 3965,3740 4990,3740 4995,3735 4985,3725 4985,3480 4330,3480 4325,3485 4325,3220 4320,3215 3835,3215 3830,3220 3850,3240 3850,3285 3855,3290 3965,3290
GND on Top Layer (solid, remove dead copper, pour order 204): 4865,4840 4880,4855 4880,5150 4885.27,5155.27 5111.53,5155.27 5130,5136.81 5130,5030 5125,5035 5000,5035 5000,4860 4980,4840
$1N109 on Top Layer (solid, remove dead copper, pour order 206): 5455,4735 5800,4735 5810,4725 5810,4610 5670,4610 5660,4600 5660,4485 5665,4480 5615,4430 5615,4190 5168.62,4190 5130,4228.62 5130,4505 5165,4540 5315,4540 5320,4535 5335.06,4550.06 5457.56,4540 5457.56,4572.47 5455,4621.68
GND on Top Layer (solid, remove dead copper, pour order 208): 4875,4530 5100,4530 5105,4525 5105,4195 5075,4165 4895,4165 4870,4190 4875,4195
$1N109 on Top Layer (solid, remove dead copper, pour order 210): 4515,3370 4800,3370 4800,3230 4520,3230 4510,3240 4515,3245
GND on Top Layer (solid, remove dead copper, pour order 212): 5670,4592.48 5827.52,4592.48 5830,4590 5830,4375 5805,4350 5685,4350 5675,4360 5675,4587.48
SW_12V on Top Layer (solid, remove dead copper, pour order 214): 6195,4995 6265,4995 6265,5040 6280,5055 6460.48,5055 6475,5040.48 6475,4850 6470,4845 6343.33,4845 6343.33,4746.31 6369.64,4720 6395,4720 6395,4610 5840,4610 5840,4775 5860,4795 6155,4795 6190,4830 6190,4861.08 6195,4866.08
ISNS+ on Top Layer (solid, remove dead copper, pour order 216): 5825,4290 6550,4290 6555,4295 6555,4105 6560,4100 5805,4100 5795,4090 5795,4260
VOUT on Top Layer (solid, remove dead copper, pour order 218): 6595,4315 6765,4315 6765,4115 6780,4100 6955,4100 6965,4090 6965,3977.82 6977.82,3965 6195,3965 6170,3990 6170,4055 6190.7,4075.7 6580.7,4075.7 6600,4095 6600,4310
GND on Top Layer (solid, remove dead copper, pour order 220): 6165,3950 6975,3950 6980,3945 6980,3845 6950,3815 6145,3815 6135,3825 6165,3855
GND on Top Layer (solid, remove dead copper, pour order 224): 3720,4295 3790,4295 3790,4245 3785,4240 3720.19,4240 3720.19,4294.81
ISNS+ on Top Layer (solid, remove dead copper, pour order 226): 6510,4775 6515,4775 6520,4780 6536.78,4780 6546.78,4770 6600,4770 6600,4759.56 6549.56,4759.56 6545,4755 6535,4755 6530,4750 6510,4750
GND on Bottom Layer (solid, remove dead copper, pour order 322): 3045,5580 3045,3085 7125,3085 7125,5580
GND on Top Layer (solid, remove dead copper, pour order 228): 3000,5585 3000,3000 7170,3000 7170,5585

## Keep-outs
Board Outline Layer:
  region: 5479.65,4911.61 5479.65,4738.39 5810.35,4738.39 5810.35,4911.61
  region: 4326.5,4663.03 4326.5,4175 4635,4175 4635,4663.03
  region: 5865,4600 5865,4300 6345,4300 6345,4600
  lines w10: 3145,3280.28 3145,5406.26 cw(c3223.74,5406.26) 3223.74,5485 6963.9,5485 cw(c6963.9,5406.26) 7042.64,5406.26 7042.64,3280.28 cw(c6963.9,3280.28) 6963.9,3201.54 3223.74,3201.54 cw(c3223.74,3280.28) 3145,3280.28 ; 3145,3280.28 3145,3280.28

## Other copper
Top Layer:
  region net GND: 3305,5445 3305,5165 4070,5165 4070,5445
  region net GND: 3662.23,4110 3662.23,4169.22 3635,4169.31 3635,4205 3640,4200 3689.59,4200 3677.7,4188.11 3677.14,4110
Inner2 (plane layer: these items are gaps in the copper):
  lines w6: 4900,5385 4900,5240 4910,5230 5010,5230 5003.64,5223.64 5003.64,4804.69 5018.32,4790 5330,4790 5330,4855 5375,4900 5375,5280 5380,5275 5560,5275 5560,5355 5580,5375 5570,5385 4902.27,5385 ; 6168.01,5053.56 6168.56,5053.56 6170,5055 ; 6374.87,4754.43 6385.83,4765.39 6487.91,4765.39 6507.51,4785 6645,4785 6650,4780 6650,4725 6634.61,4709.61 6517.35,4710.18 6517.35,4677.65 6565,4630 6565,4435 6550,4420 6550,4355 6565,4340 6565,4100 6550,4085 5835,4085 5810,4110 5810,4275 5825,4290 6375,4290 6420,4335 6420,4470 6390,4470 6375,4485 6375,4754.43 ; 4894.97,3448.54 5075,3500 5195,3620 5390,3945 5645,4080 5650,4075 5660,4085 5660,4500 5805,4500 5811.87,4506.87 5811.87,4717.16 5795.43,4733.6 5248.45,4733.6 5085,4570.14 5085,4145 4980,4040 4980,3835 4845,3700 4806.18,3700 4670.43,3564.24 4670.43,3414.57 4618.1,3414.57 4525,3385 4475,3335 4475,3240 4480,3235 4815,3235 4840,3260 4894.97,3448.54 ; 4894.97,3448.54 4895.56,3450.56 4892.97,3447.97 4894.97,3448.54 ; 3190,3250 3414.42,3250 3425,3239.42 3470,3284.42 3470,3785 3480,3795 3775,3795 3795,3775 3795,3510 3887.99,3510 3942.24,3564.24 3971.48,3535 4565,3535 4565,3625 4650,3710 4765,3710 4935,3880 4935,4060 4870,4060 4893.28,4083.28 4893.28,4685 4645,4685 4645,4675 4650,4660 4656.99,4149.59 4641.82,4148.18 4555,4148.18 4555,4036.6 4370,4036.6 4370,4140 4360.41,4149.59 4174.59,4149.59 4100,4075 4100,4065.24 3927.05,3892.28 3447.28,3892.28 3330,3775 3190,3635 3190,3250 ; 5735,3260 5760,3235 6031.78,3235 6045,3248.22 6045,3422.87 6170,3547.87 6170,3955 6918.32,3955 6928.32,3965 6928.32,4344.15 6915,4357.48 6617.48,4357.48 6605,4345 6605,4075 6600,4070 5800,4070 5735,4005 5735,3260 ; 5840,4620 5850,4610 6275,4610 6300,4635 6335,4640 6335,4803.53 6357.05,4825.57 6445.57,4825.57 6465,4845 6465,4859.34 6477.13,4871.47 6543.03,4871.47 6560.45,4854.05 6619.05,4854.05 6635,4870 6635,4896.24 6601.16,4930.08 6531.74,4930.08 6525.59,4936.23 6525.59,5053.56 6165.17,5053.56 5950,5050 5840,4940 5840,4620

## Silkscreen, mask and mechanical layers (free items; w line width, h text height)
Top Silkscreen Layer:
  lines w10: 3955.06,3305 4285,3305 ; 4034.21,3205 4034.21,3405 ; 4120.03,3205 4120.03,3405 ; 4200.87,3205 4200.87,3405 ; 5352.69,5383.9 5682.63,5383.9 ; 5353.9,5382.5 5683.84,5382.5 ; 5354.16,3303.6 5684.09,3303.6 ; 5355.03,3305 5684.97,3305 ; 5355.48,5385 5685.41,5385 ; 5433.05,5282.5 5433.05,5482.5 ; 5433.3,3203.6 5433.3,3403.6 ; 5434.18,3205 5434.18,3405 ; 5436.82,5283.9 5436.82,5483.9 ; 5439.6,5285 5439.6,5485 ; 5517.66,5283.9 5517.66,5483.9 ; 5518.87,5282.5 5518.87,5482.5 ; 5519.12,3203.6 5519.12,3403.6 ; 5520,3205 5520,3405 ; 5520.44,5285 5520.44,5485 ; 5599.71,5282.5 5599.71,5482.5 ; 5599.96,3203.6 5599.96,3403.6 ; 5600.84,3205 5600.84,3405 ; 5603.48,5283.9 5603.48,5483.9 ; 5606.27,5285 5606.27,5485 ; 6500.03,5380 6829.97,5380 ; 6501.24,5378.6 6831.18,5378.6 ; 6568.9,3298.6 6898.84,3298.6 ; 6570.03,3300 6899.97,3300 ; 6580.39,5278.6 6580.39,5478.6 ; 6584.16,5280 6584.16,5480 ; 6648.05,3198.6 6648.05,3398.6 ; 6649.18,3200 6649.18,3400 ; 6665,5280 6665,5480 ; 6666.21,5278.6 6666.21,5478.6 ; 6733.87,3198.6 6733.87,3398.6 ; 6735,3200 6735,3400 ; 6747.05,5278.6 6747.05,5478.6 ; 6750.82,5280 6750.82,5480 ; 6814.71,3198.6 6814.71,3398.6 ; 6815.84,3200 6815.84,3400 ; 3955.06,3205 3955.06,3405 4285,3405 4285,3205 3955.06,3205 ; 5352.69,5283.9 5352.69,5483.9 5682.63,5483.9 5682.63,5283.9 5352.69,5283.9 ; 5353.9,5282.5 5353.9,5482.5 5683.84,5482.5 5683.84,5282.5 5353.9,5282.5 ; 5354.16,3203.6 5354.16,3403.6 5684.09,3403.6 5684.09,3203.6 5354.16,3203.6 ; 5355.03,3205 5355.03,3405 5684.97,3405 5684.97,3205 5355.03,3205 ; 5355.48,5285 5355.48,5485 5685.41,5485 5685.41,5285 5355.48,5285 ; 6500.03,5280 6500.03,5480 6829.97,5480 6829.97,5280 6500.03,5280 ; 6501.24,5278.6 6501.24,5478.6 6831.18,5478.6 6831.18,5278.6 6501.24,5278.6 ; 6568.9,3198.6 6568.9,3398.6 6898.84,3398.6 6898.84,3198.6 6568.9,3198.6 ; 6570.03,3200 6570.03,3400 6899.97,3400 6899.97,3200 6570.03,3200
  text "GND" at 5428.84,5387.5 h50 r90
  text "GND" at 5507.17,5387.5 h50 r90
  text "GND" at 5585.51,5387.5 h50 r90
  text "GND" at 5663.84,5387.5 h50 r90
  text "GND" at 6576.18,5383.6 h50 r90
  text "GND" at 6654.51,5383.6 h50 r90
  text "GND" at 6732.84,5383.6 h50 r90
  text "GND" at 6811.18,5383.6 h50 r90
  text "24V" at 5375.48,5380 h50 r270
  text "24V" at 5453.81,5380 h50 r270
  text "24V" at 5532.14,5380 h50 r270
  text "24V" at 5610.48,5380 h50 r270
  text "12V" at 6651.18,5283.6 h50 r90
  text "12V" at 6573.71,5282.7 h50 r90
  text "12V" at 6730.38,5282.7 h50 r90
  text "12V" at 6808.71,5282.7 h50 r90
  text "24V" at 4030,3310 h50 r90
  text "24V" at 4108.33,3310 h50 r90
  text "24V" at 4186.67,3310 h50 r90
  text "24V" at 4265,3310 h50 r90
  text "12V" at 5429.09,3308.6 h50 r90
  text "12V" at 5507.43,3308.6 h50 r90
  text "12V" at 5585.76,3308.6 h50 r90
  text "12V" at 5664.09,3308.6 h50 r90
  text "5V" at 6643.84,3303.6 h50 r90
  text "5V" at 6722.17,3303.6 h50 r90
  text "5V" at 6800.51,3303.6 h50 r90
  text "5V" at 6878.84,3303.6 h50 r90
  text "GND" at 4105,3210 h50 r90
  text "GND" at 5504.97,3210 h50 r90
  text "GND" at 4027.53,3209.1 h50 r90
  text "GND" at 4184.2,3209.1 h50 r90
  text "GND" at 4262.53,3209.1 h50 r90
  text "GND" at 5427.5,3209.1 h50 r90
  text "GND" at 5504.09,3208.6 h50 r90
  text "GND" at 5584.17,3209.1 h50 r90
  text "GND" at 5662.5,3209.1 h50 r90
  text "GND" at 5426.62,3207.7 h50 r90
  text "GND" at 5583.29,3207.7 h50 r90
  text "GND" at 5661.62,3207.7 h50 r90
  text "GND" at 6719.97,3205 h50 r90
  text "GND" at 6642.5,3204.1 h50 r90
  text "GND" at 6718.84,3203.6 h50 r90
  text "GND" at 6799.17,3204.1 h50 r90
  text "GND" at 6877.5,3204.1 h50 r90
  text "GND" at 6641.37,3202.7 h50 r90
  text "GND" at 6798.04,3202.7 h50 r90
  text "GND" at 6876.37,3202.7 h50 r90
Bottom Silkscreen Layer:
  lines w10: 3550.5,3300 3945,3300 ; 3644.91,3200.79 3644.91,3399.21 ; 3745,3200.79 3745,3399.21 ; 3845,3201.57 3845,3400 ; 3955,3330 3955.06,3329.94 3955.06,3332.65 ; 3955.06,3205 3955.06,3404.94 3960,3405 4287.32,3405 4287.32,3205 ; 3955.06,3210 3955.06,3202.8 4287.32,3202.8 4287.32,3210 ; 3955.06,3300 4285,3300 ; 4034.21,3205 4034.21,3405 ; 4120.03,3205 4120.03,3405 ; 4200.94,3205 4200.94,3405 ; 4949.34,5382.5 5343.84,5382.5 ; 4949.59,3298.6 5344.09,3298.6 ; 5043.75,5283.29 5043.75,5481.71 ; 5044.01,3199.39 5044.01,3397.81 ; 5143.84,5283.29 5143.84,5481.71 ; 5144.09,3199.39 5144.09,3397.81 ; 5243.84,5284.07 5243.84,5482.5 ; 5244.09,3200.18 5244.09,3398.6 ; 5353.84,5482.5 5353.9,5482.44 5353.9,5485.15 ; 5353.9,5287.5 5353.9,5487.44 5358.84,5487.5 5686.16,5487.5 5686.16,5287.5 ; 5353.9,5292.5 5353.9,5285.3 5686.16,5285.3 5686.16,5292.5 ; 5353.9,5382.5 5683.84,5382.5 ; 5354.09,3323.6 5354.16,3323.54 5354.16,3326.26 ; 5354.16,3203.6 5354.16,3403.54 5359.09,3403.6 5686.41,3403.6 5686.41,3203.6 ; 5354.16,3208.6 5354.16,3201.4 5686.41,3201.4 5686.41,3208.6 ; 5354.16,3298.6 5684.09,3298.6 ; 5433.05,5287.5 5433.05,5487.5 ; 5433.3,3203.6 5433.3,3403.6 ; 5518.87,5287.5 5518.87,5487.5 ; 5519.12,3203.6 5519.12,3403.6 ; 5599.78,5287.5 5599.78,5487.5 ; 5600.03,3203.6 5600.03,3403.6 ; 6096.67,5378.6 6491.18,5378.6 ; 6164.34,3298.6 6558.84,3298.6 ; 6191.09,5279.39 6191.09,5477.81 ; 6258.75,3199.39 6258.75,3397.81 ; 6291.18,5279.39 6291.18,5477.81 ; 6358.84,3199.39 6358.84,3397.81 ; 6391.18,5280.18 6391.18,5478.6 ; 6458.84,3200.18 6458.84,3398.6 ; 6501.18,5478.6 6501.24,5478.54 6501.24,5481.26 ; 6501.24,5283.6 6501.24,5483.54 6506.18,5483.6 6833.5,5483.6 6833.5,5283.6 ; 6501.24,5288.6 6501.24,5281.4 6833.5,5281.4 6833.5,5288.6 ; 6501.24,5378.6 6831.18,5378.6 ; 6568.84,3323.6 6568.9,3323.54 6568.9,3326.26 ; 6568.9,3203.6 6568.9,3403.54 6573.84,3403.6 6901.16,3403.6 6901.16,3203.6 ; 6568.9,3208.6 6568.9,3201.4 6901.16,3201.4 6901.16,3208.6 ; 6568.9,3298.6 6898.84,3298.6 ; 6580.39,5283.6 6580.39,5483.6 ; 6648.05,3203.6 6648.05,3403.6 ; 6666.21,5283.6 6666.21,5483.6 ; 6733.87,3203.6 6733.87,3403.6 ; 6747.12,5283.6 6747.12,5483.6 ; 6814.78,3203.6 6814.78,3403.6 ; 3545.39,3200 3545.39,3201.57 ; 3545.39,3200 3545.39,3201.57 ; 3545.39,3200 3545.39,3201.57 ; 3545.39,3201.57 3945,3201.57 3945,3405 3545,3405 3545.39,3404.61 3545.39,3201.57 ; 4944.23,5282.5 4944.23,5284.07 ; 4944.23,5282.5 4944.23,5284.07 ; 4944.23,5282.5 4944.23,5284.07 ; 4944.23,5284.07 5343.84,5284.07 5343.84,5487.5 4943.84,5487.5 4944.23,5487.11 4944.23,5284.07 ; 4944.49,3198.6 4944.49,3200.18 ; 4944.49,3198.6 4944.49,3200.18 ; 4944.49,3198.6 4944.49,3200.18 ; 4944.49,3200.18 5344.09,3200.18 5344.09,3403.6 4944.09,3403.6 4944.49,3403.21 4944.49,3200.18 ; 6091.57,5278.6 6091.57,5280.18 ; 6091.57,5278.6 6091.57,5280.18 ; 6091.57,5278.6 6091.57,5280.18 ; 6091.57,5280.18 6491.18,5280.18 6491.18,5483.6 6091.18,5483.6 6091.57,5483.21 6091.57,5280.18 ; 6159.23,3198.6 6159.23,3200.18 ; 6159.23,3198.6 6159.23,3200.18 ; 6159.23,3198.6 6159.23,3200.18 ; 6159.23,3200.18 6558.84,3200.18 6558.84,3403.6 6158.84,3403.6 6159.23,3403.21 6159.23,3200.18
  text "GND" at 5421.34,5473.3 h40 r90
  text "GND" at 5499.67,5473.3 h40 r90
  text "GND" at 5656.34,5473.3 h40 r90
  text "GND" at 5578.87,5472.4 h40 r90
  text "GND" at 6568.68,5469.4 h40 r90
  text "GND" at 6647.01,5469.4 h40 r90
  text "GND" at 6726.21,5468.5 h40 r90
  text "GND" at 6803.68,5469.4 h40 r90
  text "VIN" at 5421.37,5362.19 h40 r90
  text "VIN" at 5499.71,5362.19 h40 r90
  text "VIN" at 5656.37,5362.19 h40 r90
  text "VIN" at 5578.91,5361.29 h40 r90
  text "VIN" at 6568.71,5358.29 h40 r90
  text "VIN" at 6647.04,5358.29 h40 r90
  text "VIN" at 6803.71,5358.29 h40 r90
  text "VIN" at 6726.24,5357.39 h40 r90
  text "48V转24V转12V转5V / DCDC降压模块" at 5805,4570 h200
  text "VOUT" at 4059.97,3306 h40 r270
  text "VOUT" at 3982.5,3305.1 h40 r270
  text "VOUT" at 4139.17,3305.1 h40 r270
  text "VOUT" at 4217.5,3305.1 h40 r270
  text "VOUT" at 5459.06,3304.6 h40 r270
  text "VOUT" at 6673.81,3304.6 h40 r270
  text "VOUT" at 5381.59,3303.7 h40 r270
  text "VOUT" at 5538.26,3303.7 h40 r270
  text "VOUT" at 5616.59,3303.7 h40 r270
  text "VOUT" at 6596.34,3303.7 h40 r270
  text "VOUT" at 6753.01,3303.7 h40 r270
  text "VOUT" at 6831.34,3303.7 h40 r270
  text "GND" at 6596.37,3212.59 h40 r270
  text "GND" at 4060,3209.89 h40 r270
  text "GND" at 3982.53,3208.99 h40 r270
  text "GND" at 4139.2,3208.99 h40 r270
  text "GND" at 4217.53,3208.99 h40 r270
  text "GND" at 5381.62,3207.59 h40 r270
  text "GND" at 5459.09,3208.49 h40 r270
  text "GND" at 5538.29,3207.59 h40 r270
  text "GND" at 5616.62,3207.59 h40 r270
  text "GND" at 6673.84,3208.49 h40 r270
  text "GND" at 6753.04,3207.59 h40 r270
  text "GND" at 6831.37,3207.59 h40 r270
